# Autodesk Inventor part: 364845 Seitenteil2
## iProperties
Company: Hundt & Weber AG Schaltgeräte
Created: 2010-11
Part Number: 364845 Seitenteil2
Material: 1.0120
Document SubType Name: Modeling
Designer: I.Baliuc
Manufacturer: Standard
Standards Organization: Custom
Description: Seitenteil, Trenner
Cost Center: 5,196 kg
Authority: 661896 mm^3
Density: 7.85 g/cm^3
HalbzeugNorm: DIN 174
Zweck: HSLT / HSE - Standardseite
Abmessung: Fl. 120x12-170
SaveDate: 2006-10-28
SaveTime: 20:23
TotalMass: 5,196 kg
TotalVolume: 661896 mm^3
Author: AHausen
Revision Number: 364845
Keywords: 380125
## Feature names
1. Extrusion2
2. Bohrung_Ø13 [Hole]
3. Bohrung2 [Hole]
4. Bohrung3 [Hole]
5. Bohrung_M8_01 [Hole]
6. Bohrung_M8_02 [Hole]
7. Bohrung_M6 [Hole]
8. Bohrung_M5 [Hole]
9. Neue Bohrung (zusätzlich) [Rectangular Pattern]
